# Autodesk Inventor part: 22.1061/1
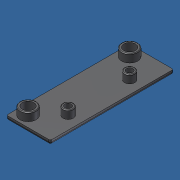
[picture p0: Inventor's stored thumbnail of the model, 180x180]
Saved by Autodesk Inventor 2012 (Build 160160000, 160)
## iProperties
Created: 2007-01
Part Number: 22.1061/1
Document SubType Name: Modeling
Designer: Andy Moles
Material: ABS Plastic
Density: 1.06 g/cm^3
Mass: 10.0172 g
Surface Area: 75.0145 cm^2
Volume: 9.45016 cm^3
Description: END CAP 90X32 GRAY
Vendor: S
Author: Andy Moles
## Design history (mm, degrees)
sketch "Sketch1"
  geometry: L1 (-22.5, 45)-(9.5, 45); L2 (9.5, 45)-(9.5, -45); L3 (9.5, -45)-(-22.5, -45); L4 (-22.5, -45)-(-22.5, 45); 1 further point
  constraints: 8 end point, 2 parallel, 1 horizontal, 1 perpendicular
  dimensions: "WIDTH1" = 90 distance of L1.end L2.end; "WIDTH2" = 32 distance of L1.start L1.end; "d2" = 45 distance from line of point (0, 0) L1; "d3" = 9.5 distance from line of point (0, 0) L2
extrude "Extrusion1" new body sketch "Sketch1" distance "d4" = 3; taper "d5" = 0 deg
fillet "Fillet1" dims "d6" = 1
fillet "Fillet2" dims "d7" = 1.5
sketch "Sketch2"
  geometry: L1 (9.5, 44)-(9.5, -44) reference; L2 (-21.5, 45)-(8.5, 45) reference; L3 (-22.5, -44)-(-22.5, 44) reference; C1 r 3.825 at (0, 22.5); C2 r 2.375 at (0, 22.5); C3 r 4.25 at (-14.65, 37.15); C4 r 5.875 at (-14.65, 37.15)
  constraints: 4 centre point, 2 coincident
  dimensions: "d8" = 4.75 diameter of C2; "d9" = 7.65 diameter of C1; "d10" = 8.5 diameter of C3; "d11" = 11.75 diameter of C4; "d12" = 22.5 distance from line of C1.centre L2; "d13" = 9.5 distance from line of C1.centre L1; "d14" = 7.85 distance from line of C3.centre L2; "d15" = 7.85 distance from line of C3.centre L3
extrude "Extrusion2" join sketch "Sketch2" distance "d16" = 5.85; taper "d17" = 0 deg
fillet "Fillet3" dims "d18" = 0.5
mirror "Mirror1"
body "Solid1"
